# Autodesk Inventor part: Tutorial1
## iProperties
Shininess: 64.0
Length Units: 11269
Angle Units: 11279
Time Units: 11290
Mass Units: 11283
Length Display Precision: 3
Angle Display Precision: 2
Compacted: True
Part Number: Tutorial1
Document SubType Name: Modeling
Created: 2002-11
Designer: deepak
Density: 1 g/cm^3
Density: 0.0
Volumn: 0.0
Area: 0.0
PropertySet Name: Model Information
Control State: 0
Master: False
Checked Out: False
Author: deepak
